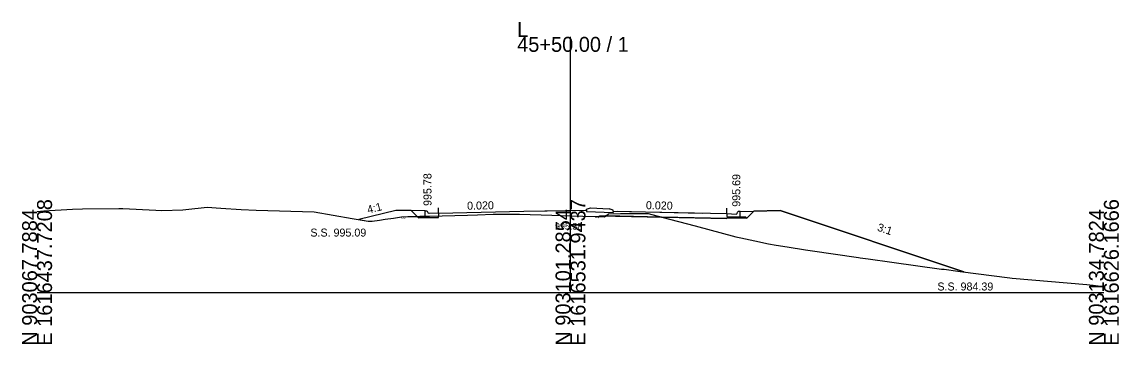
# Model space of a CAD drawing. Extents: x 1009 to 7438, y -1586 to 7964.
# Drawn here: x 4032.1 to 4237.7, y 3414 to 3474.4 of the extents above; entities that cross this region are included whole.
import ezdxf

# ---------------------------------------------------------------- set-up
doc = ezdxf.new("R2010")
doc.units = 0
for name, color, linetype in [('Exist Cross Section Cell', 7, 'Continuous'), ('Exist XS Center Line Elevation Label', 7, 'Continuous'), ('Exist XS Ground Line', 7, 'Continuous'), ('Prop XS Dump Level', 7, 'Continuous'), ('Prop XS Earthwork Shape', 7, 'Continuous'), ('Prop XS EOT Tick Mark', 7, 'Continuous'), ('Prop XS Finish Grade', 7, 'Continuous'), ('Prop XS Finish Grade CurbGutter', 7, 'Continuous'), ('Prop XS Finish Grade Earthwork', 7, 'Continuous'), ('Prop XS Finish Grade Pavement', 7, 'Continuous'), ('Prop XS Hydro Elevations', 7, 'Continuous'), ('Prop XS Pvmt Edge Slope', 7, 'Continuous'), ('Prop XS SE Text', 7, 'Continuous'), ('Prop XS Side Slope Text', 7, 'Continuous'), ('Prop XS SS Elevation Text', 7, 'Continuous'), ('Prop XS Subgrade CurbGutter', 7, 'Continuous'), ('Prop XS Subgrade Earthwork', 7, 'Continuous')]:
    doc.layers.add(name, color=color, linetype=linetype)

msp = doc.modelspace()

# ---------------------------------------------------------------- linework, layer by layer
at = {"layer": 'Exist Cross Section Cell'}
for p, q in [((4134.89, 3423.73), (4134.89, 3471.63)), ((4034.89, 3423.73), (4134.89, 3423.73)), ((4134.89, 3423.73), (4234.89, 3423.73))]:
    msp.add_line(p, q, dxfattribs=at)
at = {"layer": 'Exist XS Ground Line'}
for p, q in [((4034.89, 3438.87), (4036.18, 3439)), ((4036.18, 3439), (4041.53, 3439.3)), ((4041.53, 3439.3), (4043.38, 3439.39)), ((4043.38, 3439.39), (4050.19, 3439.48)), ((4050.19, 3439.48), (4050.94, 3439.47)), ((4050.94, 3439.47), (4057.18, 3439.14)), ((4057.18, 3439.14), (4058.27, 3439.07)), ((4058.27, 3439.07), (4062.19, 3439.19)), ((4062.19, 3439.19), (4062.77, 3439.26)), ((4062.77, 3439.26), (4066.79, 3439.7)), ((4066.79, 3439.7), (4069.36, 3439.5)), ((4069.36, 3439.5), (4073.16, 3439.24)), ((4073.16, 3439.24), (4075.99, 3439.17)), ((4075.99, 3439.17), (4086.85, 3438.83)), ((4086.85, 3438.83), (4093.94, 3437.59)), ((4093.94, 3437.59), (4096.95, 3437.08)), ((4096.95, 3437.08), (4097.7, 3437.08)), ((4097.7, 3437.08), (4099.07, 3437.28)), ((4099.07, 3437.28), (4100.14, 3437.43)), ((4100.14, 3437.43), (4101.73, 3437.67)), ((4101.73, 3437.67), (4103.2, 3437.87)), ((4103.2, 3437.87), (4104.39, 3437.93)), ((4104.39, 3437.93), (4108.47, 3438.03)), ((4108.47, 3438.03), (4115.59, 3438.22)), ((4115.59, 3438.22), (4117.44, 3438.29)), ((4117.44, 3438.29), (4120.38, 3438.4)), ((4120.38, 3438.4), (4123.29, 3438.4)), ((4123.29, 3438.4), (4125.3, 3438.4)), ((4125.3, 3438.4), (4131.38, 3438.22)), ((4131.38, 3438.22), (4134.89, 3438.11)), ((4134.89, 3438.11), (4139.51, 3437.97)), ((4139.51, 3437.97), (4140.31, 3437.94)), ((4140.31, 3437.94), (4141.29, 3437.91)), ((4141.29, 3437.91), (4141.61, 3438.15)), ((4141.61, 3438.15), (4142.01, 3438.45)), ((4142.01, 3438.45), (4144.28, 3438.49)), ((4144.28, 3438.49), (4147.03, 3438.53)), ((4147.03, 3438.53), (4148.87, 3438.53)), ((4148.87, 3438.53), (4149.44, 3438.53)), ((4149.44, 3438.53), (4151.99, 3437.84)), ((4151.99, 3437.84), (4158.27, 3436.2)), ((4158.27, 3436.2), (4165.91, 3434.12)), ((4165.91, 3434.12), (4166.81, 3433.93)), ((4166.81, 3433.93), (4169.43, 3433.42)), ((4169.43, 3433.42), (4172.04, 3432.85)), ((4172.04, 3432.85), (4173.47, 3432.59)), ((4173.47, 3432.59), (4175.54, 3432.28)), ((4175.54, 3432.28), (4178.97, 3431.69)), ((4178.97, 3431.69), (4179.83, 3431.58)), ((4179.83, 3431.58), (4188.87, 3430.27)), ((4188.87, 3430.27), (4189.22, 3430.22)), ((4189.22, 3430.22), (4190.68, 3430.01)), ((4190.68, 3430.01), (4195.11, 3429.39)), ((4195.11, 3429.39), (4204.42, 3428.11)), ((4204.42, 3428.11), (4204.95, 3428.05)), ((4204.95, 3428.05), (4207.51, 3427.72)), ((4207.51, 3427.72), (4207.95, 3427.66)), ((4207.95, 3427.66), (4217.24, 3426.45)), ((4217.24, 3426.45), (4217.69, 3426.4)), ((4217.69, 3426.4), (4231.72, 3425.19)), ((4231.72, 3425.19), (4232.85, 3425.1)), ((4232.85, 3425.1), (4233.83, 3424.98)), ((4233.83, 3424.98), (4234.89, 3424.91))]:
    msp.add_line(p, q, dxfattribs=at)
at = {"layer": 'Prop XS Dump Level'}
for p, q in [((4126.14, 3438.93), (4134.89, 3439.11)), ((4126.14, 3438.93), (4134.89, 3439.11)), ((4110.14, 3438.61), (4126.14, 3438.93)), ((4110.14, 3438.61), (4126.14, 3438.93)), ((4143.64, 3438.93), (4159.64, 3438.61)), ((4143.64, 3438.93), (4159.64, 3438.61))]:
    msp.add_line(p, q, dxfattribs=at)
at = {"layer": 'Prop XS Earthwork Shape'}
for points in [[(4105.05, 3439.05), (4102.14, 3439.11), (4095.21, 3437.38), (4096.95, 3437.08), (4097.7, 3437.08), (4099.07, 3437.28), (4100.14, 3437.43), (4101.73, 3437.67), (4103.2, 3437.87), (4104.39, 3437.93), (4106.13, 3437.97)], [(4178.97, 3431.69), (4179.83, 3431.58), (4188.87, 3430.27), (4189.22, 3430.22), (4190.68, 3430.01), (4195.11, 3429.39), (4204.42, 3428.11), (4204.95, 3428.05), (4207.51, 3427.72), (4207.95, 3427.66), (4208.65, 3427.57), (4174.19, 3439.06), (4169.28, 3438.96), (4167.94, 3437.62), (4164.19, 3437.69), (4164.19, 3437.61), (4151.95, 3437.85), (4151.99, 3437.84), (4158.27, 3436.2), (4165.91, 3434.12), (4166.81, 3433.93), (4169.43, 3433.42), (4172.04, 3432.85), (4173.47, 3432.59), (4175.54, 3432.28)], [(4107.64, 3437.98), (4106.64, 3437.96), (4106.39, 3437.71), (4106.13, 3437.97), (4107.64, 3438.01)], [(4107.64, 3437.98), (4106.64, 3437.96), (4106.39, 3437.71), (4110.14, 3437.78), (4110.14, 3438.03)], [(4110.14, 3438.03), (4107.64, 3437.98), (4107.64, 3438.01), (4108.47, 3438.03), (4110.14, 3438.08)], [(4140.31, 3437.94), (4140.31, 3438.08), (4141.49, 3438.06), (4141.29, 3437.91)], [(4144.28, 3438.49), (4147.03, 3438.53), (4148.87, 3438.53), (4149.44, 3438.53), (4151.95, 3437.85), (4141.49, 3438.06), (4141.61, 3438.15), (4142.01, 3438.45)]]:
    msp.add_lwpolyline(points, close=True, dxfattribs=at)
at = {"layer": 'Prop XS EOT Tick Mark'}
for p, q in [((4110.14, 3438.61), (4110.14, 3439.61)), ((4164.19, 3438.52), (4164.19, 3439.52))]:
    msp.add_line(p, q, dxfattribs=at)
at = {"layer": 'Prop XS Finish Grade'}
for p, q in [((4107.64, 3438.99), (4105.05, 3439.05)), ((4166.69, 3438.9), (4169.28, 3438.96))]:
    msp.add_line(p, q, dxfattribs=at)
at = {"layer": 'Prop XS Finish Grade CurbGutter'}
for p, q in [((4137.89, 3439.34), (4138.64, 3439.59)), ((4137.89, 3439.17), (4137.89, 3439.34)), ((4138.64, 3439.59), (4142.14, 3439.37)), ((4142.89, 3439.12), (4142.14, 3439.37)), ((4142.89, 3438.95), (4142.89, 3439.12)), ((4107.64, 3438.99), (4107.89, 3438.99)), ((4107.89, 3438.99), (4108.02, 3438.97)), ((4108.11, 3438.87), (4108.02, 3438.97)), ((4108.18, 3438.62), (4108.11, 3438.87)), ((4108.27, 3438.53), (4108.18, 3438.62)), ((4108.39, 3438.51), (4108.27, 3438.53)), ((4110.14, 3438.61), (4108.39, 3438.51)), ((4164.19, 3438.52), (4165.94, 3438.42)), ((4165.94, 3438.42), (4166.06, 3438.44)), ((4166.06, 3438.44), (4166.15, 3438.53)), ((4166.15, 3438.53), (4166.22, 3438.78)), ((4166.22, 3438.78), (4166.31, 3438.87)), ((4166.44, 3438.9), (4166.31, 3438.87)), ((4166.69, 3438.9), (4166.44, 3438.9))]:
    msp.add_line(p, q, dxfattribs=at)
at = {"layer": 'Prop XS Finish Grade Earthwork'}
for p, q in [((4102.14, 3439.11), (4095.21, 3437.38)), ((4105.05, 3439.05), (4102.14, 3439.11)), ((4169.28, 3438.96), (4174.19, 3439.06)), ((4174.19, 3439.06), (4208.65, 3427.57))]:
    msp.add_line(p, q, dxfattribs=at)
at = {"layer": 'Prop XS Finish Grade Pavement'}
for p, q in [((4126.14, 3438.93), (4137.89, 3439.17)), ((4110.14, 3438.61), (4126.14, 3438.93)), ((4142.89, 3438.95), (4164.19, 3438.52))]:
    msp.add_line(p, q, dxfattribs=at)
at = {"layer": 'Prop XS Pvmt Edge Slope'}
for p, q in [((4106.64, 3437.96), (4106.39, 3437.71)), ((4107.64, 3437.98), (4106.64, 3437.96)), ((4166.69, 3437.89), (4167.69, 3437.87)), ((4167.69, 3437.87), (4167.94, 3437.62))]:
    msp.add_line(p, q, dxfattribs=at)
at = {"layer": 'Prop XS Subgrade CurbGutter'}
for p, q in [((4137.89, 3439.17), (4137.89, 3438.92)), ((4107.64, 3437.98), (4107.64, 3438.99)), ((4110.14, 3438.03), (4107.64, 3437.98)), ((4110.14, 3438.61), (4110.14, 3438.03)), ((4137.89, 3438.92), (4142.89, 3438.7)), ((4142.89, 3438.95), (4142.89, 3438.7)), ((4164.19, 3438.52), (4164.19, 3437.94)), ((4164.19, 3437.94), (4166.69, 3437.89)), ((4166.69, 3437.89), (4166.69, 3438.9))]:
    msp.add_line(p, q, dxfattribs=at)
at = {"layer": 'Prop XS Subgrade Earthwork'}
for p, q in [((4106.39, 3437.71), (4105.05, 3439.05)), ((4110.14, 3437.78), (4106.39, 3437.71)), ((4110.14, 3437.78), (4110.14, 3438.08)), ((4140.31, 3437.94), (4140.31, 3438.08)), ((4140.31, 3438.08), (4164.19, 3437.61)), ((4164.19, 3437.61), (4164.19, 3437.69)), ((4164.19, 3437.69), (4167.94, 3437.62)), ((4167.94, 3437.62), (4169.28, 3438.96))]:
    msp.add_line(p, q, dxfattribs=at)

# ---------------------------------------------------------------- texts
at = {"layer": 'Exist Cross Section Cell'}
for s, p in [('L', (4124.89, 3471.63)), ('45+50.00 / 1', (4124.89, 3468.83))]:
    msp.add_text(s, height=2.8, dxfattribs=at).set_placement(p)
for s, p in [('N 903067.7884', (4034.89, 3413.73)), ('E 1616437.7208', (4037.69, 3413.73)), ('N 903101.2854', (4134.89, 3413.73)), ('E 1616531.9437', (4137.69, 3413.73)), ('N 903134.7824', (4234.89, 3413.73)), ('E 1616626.1666', (4237.69, 3413.73))]:
    msp.add_text(s, height=2.8, rotation=90, dxfattribs=at).set_placement(p)
at = {"layer": 'Exist XS Center Line Elevation Label'}
msp.add_text('995.38', height=1.25, dxfattribs=at).set_placement((4131.99, 3435.49))
at = {"layer": 'Prop XS Dump Level'}
for p in [(4103.2, 3437.57), (4139.51, 3437.67), (4139.51, 3437.67), (4139.51, 3437.67)]:
    msp.add_text('Eop', height=0.3, dxfattribs=at).set_placement(p)
at = {"layer": 'Prop XS Hydro Elevations'}
for s, p in [('995.78', (4108.83, 3439.93)), ('995.69', (4166.72, 3439.78))]:
    msp.add_text(s, height=1.5, rotation=90, dxfattribs=at).set_placement(p)
at = {"layer": 'Prop XS SE Text'}
for rotation, p in [(1.1458, (4115.52, 3439.22)), (358.8542, (4149.02, 3439.33))]:
    msp.add_text('0.020', height=1.5, rotation=rotation, dxfattribs=at).set_placement(p)
at = {"layer": 'Prop XS Side Slope Text'}
for s, rotation, p in [('4:1', 14.0362, (4096.96, 3438.48)), ('3:1', 341.5651, (4192.28, 3435.32))]:
    msp.add_text(s, height=1.5, rotation=rotation, dxfattribs=at).set_placement(p)
at = {"layer": 'Prop XS SS Elevation Text'}
for s, p in [('S.S. 995.09', (4086.12, 3434.19)), ('S.S. 984.39', (4203.67, 3424.08))]:
    msp.add_text(s, height=1.5, dxfattribs=at).set_placement(p)

doc.saveas('drawing.dxf')
